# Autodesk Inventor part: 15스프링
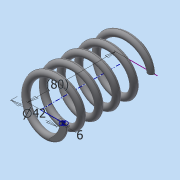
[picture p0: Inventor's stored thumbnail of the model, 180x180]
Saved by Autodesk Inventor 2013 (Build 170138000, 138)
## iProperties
Created: 2019-10
Part Number: 15스프링
Material: 일반
Document SubType Name: Modeling
Designer: dgall
Density: 1 g/cm^3
Author: dgall
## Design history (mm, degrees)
sketch "스케치1"
  geometry: L1 (21, 0)-(0, 0); L2 (0, 0)-(0, 67.25); L3 (0, 67.25)-(26.364, 67.25); C1 r 3 at (21, 0)
  constraints: 6 end point, 1 centre point, 1 coincident, 1 horizontal, 1 parallel, 1 perpendicular
  dimensions: "d0" = 6 diameter of C1; "d2" = 67.25 distance between parallel lines of L1 L3 (derived); "d3" = 42 diameter of C1.centre L2
feature "코일1" pitch "d4" = 10; turns "d6" = 5; dims "d5" = 67.25 (= d2), "d7" = 0, angle "d8" = 90 deg, angle "d9" = 90 deg, "d10" = 0, "d11" = 0
feature "분할1"
node "작업 평면1"
feature "분할2"
node "솔리드1"
other parameters: "d12" = 0
